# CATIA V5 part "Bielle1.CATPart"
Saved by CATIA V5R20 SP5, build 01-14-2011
Part number: Bielle1
Bounding box of the stored display mesh (mm): x 0 to 3, y -2 to 10, z -1.97 to 1.97
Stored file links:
  F:\PROJ IAO\CATIA\Bielle1.CATPart
  F:\PROJ IAO\CATIA\Assemblage.CATProduct
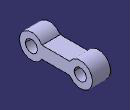
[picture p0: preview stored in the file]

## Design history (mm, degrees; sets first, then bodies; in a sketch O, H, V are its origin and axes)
Set1
  Plane1: linked copy from another document
  Line1: linked copy from another document
  Point1: linked copy from another document
Body1 (main body)
  Sketch1 on Plane1, origin (0, 0, 0), H (0, 1, 0), V (0, 0, 1)
    arc A1 centre (0, 0) radius 2 from (1.7321, 1) to (1.7321, -1) ccw
    arc A2 centre (8, 0) radius 2 from (6.2679, -1) to (6.2679, 1) ccw
    point P1 (8, 0)
    line L1 (6.2679, 1) -> (1.7321, 1)
    point P2 (6.2679, 1)
    point P3 (1.7321, 1)
    line L2 (6.2679, -1) -> (1.7321, -1)
    point P4 (6.2679, -1)
    point P5 (1.7321, -1)
    reference projected line E1 (8, 0) -> (0, 0) from Line1
    reference projected point E2 (8, 0) from Point1
    point P6 (6.2679, 1)
    reference projected line E3 (8, 0) -> (0, 0) from Line1
    reference projected line E4 (8, 0) -> (0, 0) from Line1
    circle A3 centre (8, 0) radius 1
    circle A4 centre (0, 0) radius 1
    construction line L3 (0, 2) -> (8, 2)
    point P7 (0, 2)
    point P8 (8, 2)
    construction line L4 (8, 4) -> (8, -3)
    reference projected point E5 (8, 0) from Point1
    axis line L5 (8, 1) -> (0, 1)
    point P11 (8, 1)
    point P12 (0, 1)
    radius A1 = 2
    radius A4 = 1
    distance L1 L2 = 2
    coincidence: P1 H, P1 E2, P6 P2, P8 A2, P7 A1, P7 V, L4 E5, P8 L4, P12 A4, P11 A3, P11 L4, P12 V
    horizontal: L1 H, L2 H, L3 H, L5 H
    symmetry: L2 L1 E1, P2 P4 E3, P3 P5 E4
    vertical: L4 V
  Pad1: profile Sketch1, direction (1, 0, 0), length 3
